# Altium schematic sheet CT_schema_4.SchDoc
size 283 x 147 mm
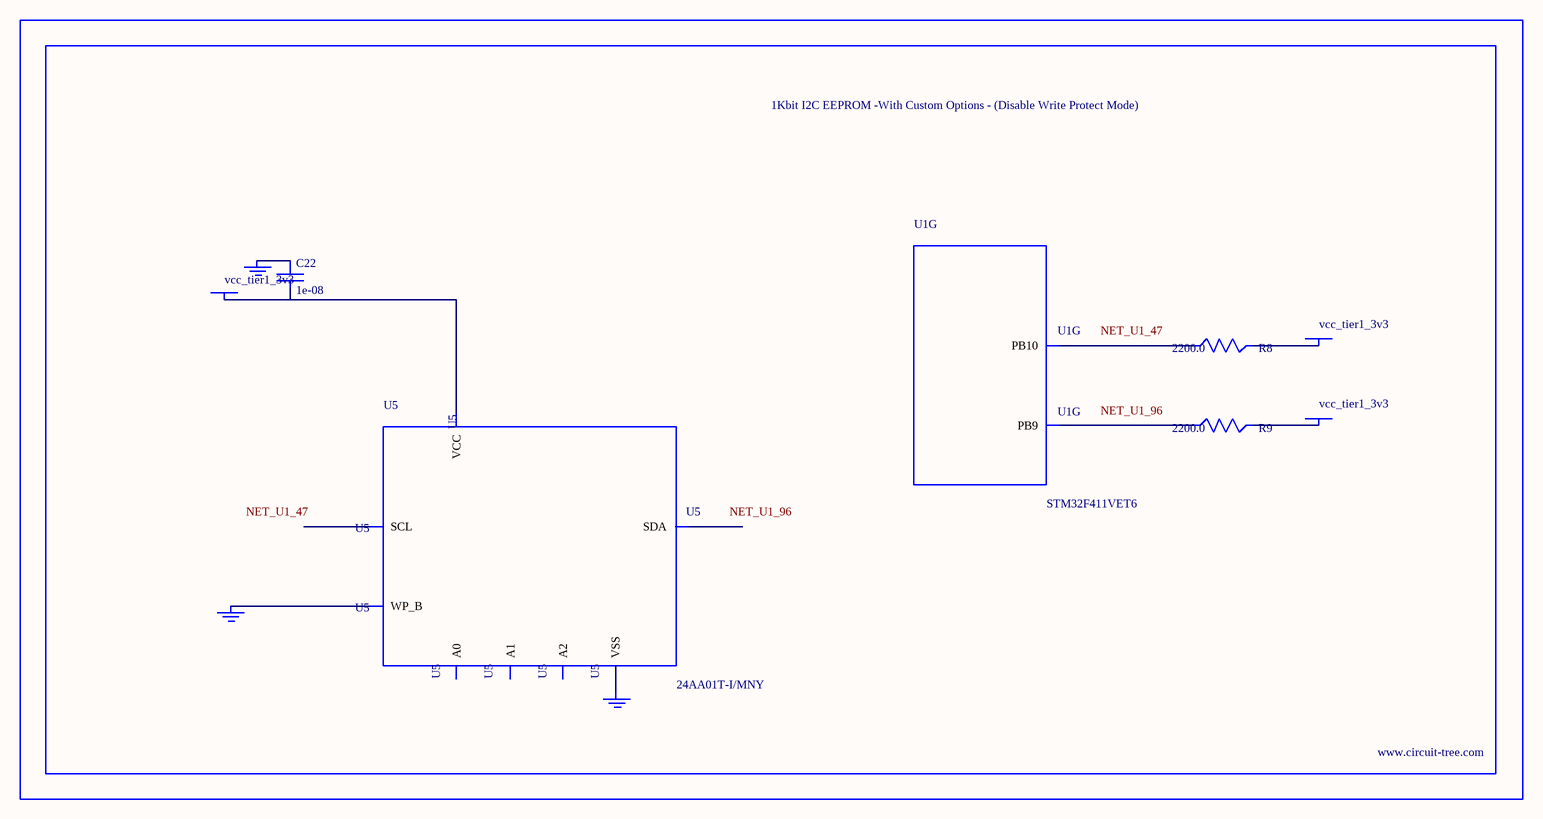
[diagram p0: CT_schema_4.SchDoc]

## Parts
BORDER3  (no value)
C22  1e-08  [C0402]
GND_INSTANCE_3_0  (no value)
GND_INSTANCE_3_1  (no value)
GND_INSTANCE_3_2  (no value)
POWER_INSTANCE_3_0  vcc_tier1_3v3
POWER_INSTANCE_3_1  vcc_tier1_3v3
POWER_INSTANCE_3_2  vcc_tier1_3v3
R8  2200.0  [R0603]
R9  2200.0  [R0603]
U1  STM32F411VET6  [LQFP100]  (part G of 10)
U5  24AA01T-I/MNY  [TDFN-8/6MM]

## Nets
NetC22_1: C22.1 GND_INSTANCE_3_1.0(GND)
NetC22_2: C22.2 POWER_INSTANCE_3_0.0(PWR) U5.8(VCC)
NetGND_INSTANCE_3_0_0: GND_INSTANCE_3_0.0(GND) U5.7(WP_B)
NetGND_INSTANCE_3_2_0: GND_INSTANCE_3_2.0(GND) U5.4(VSS)
NetPOWER_INSTANCE_3_1_0: POWER_INSTANCE_3_1.0(PWR) R8.2
NetPOWER_INSTANCE_3_2_0: POWER_INSTANCE_3_2.0(PWR) R9.2
NetR8_1: R8.1 U1.47(PB10)
NetR9_1: R9.1 U1.96(PB9)

Not connected (* = marked no-connect by the designer): U5 1(A0) 2(A1) 3(A2) 5(SDA) 6(SCL)

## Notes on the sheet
- Labels drawn without touching a wire or pin: NET_U1_47, NET_U1_96

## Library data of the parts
BORDER3 = BORDER_PAGE3
C22 = C0402C103K3RAC
GND_INSTANCE_3_0-GND_INSTANCE_3_2 = GND
POWER_INSTANCE_3_0-POWER_INSTANCE_3_2 = PWR
R8 R9 = RC0603JR-072K2L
